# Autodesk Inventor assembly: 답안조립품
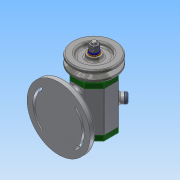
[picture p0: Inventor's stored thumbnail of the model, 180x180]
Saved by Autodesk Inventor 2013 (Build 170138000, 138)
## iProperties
Created: 2017-06
Part Number: 답안조립품
Document SubType Name: Assembly
Designer: Administrator
Author: Administrator
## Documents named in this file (14)
- C:\Users\Administrator\Desktop\470608V1012\답안조립품.iam
- C:\Users\Administrator\Desktop\470608V1012\본체.ipt
- C:\Users\Administrator\Desktop\470608V1012\V벨트풀리.ipt
- C:\Users\Administrator\Desktop\470608V1012\고무캡.ipt
- C:\Users\Administrator\Desktop\470608V1012\너트 M 8.ipt
- C:\Users\Administrator\Desktop\470608V1012\뒤커버.ipt
- C:\Users\Administrator\Desktop\470608V1012\베어링 15 x 32 x 9.ipt
- C:\Users\Administrator\Desktop\470608V1012\볼트 M4 x 12.ipt
- C:\Users\Administrator\Desktop\470608V1012\스프링와셔 8.ipt
- C:\Users\Administrator\Desktop\470608V1012\앞커버.ipt
- C:\Users\Administrator\Desktop\470608V1012\오일 실 15 25 7.ipt
- C:\Users\Administrator\Desktop\470608V1012\와셔 8x17.ipt
- C:\Users\Administrator\Desktop\470608V1012\축.ipt
- C:\Users\Administrator\Desktop\470608V1012\키 3 x 3 x 12.ipt
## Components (2 placed, 2 different names)
1. V벨트풀리:1
2. 고무캡:1
